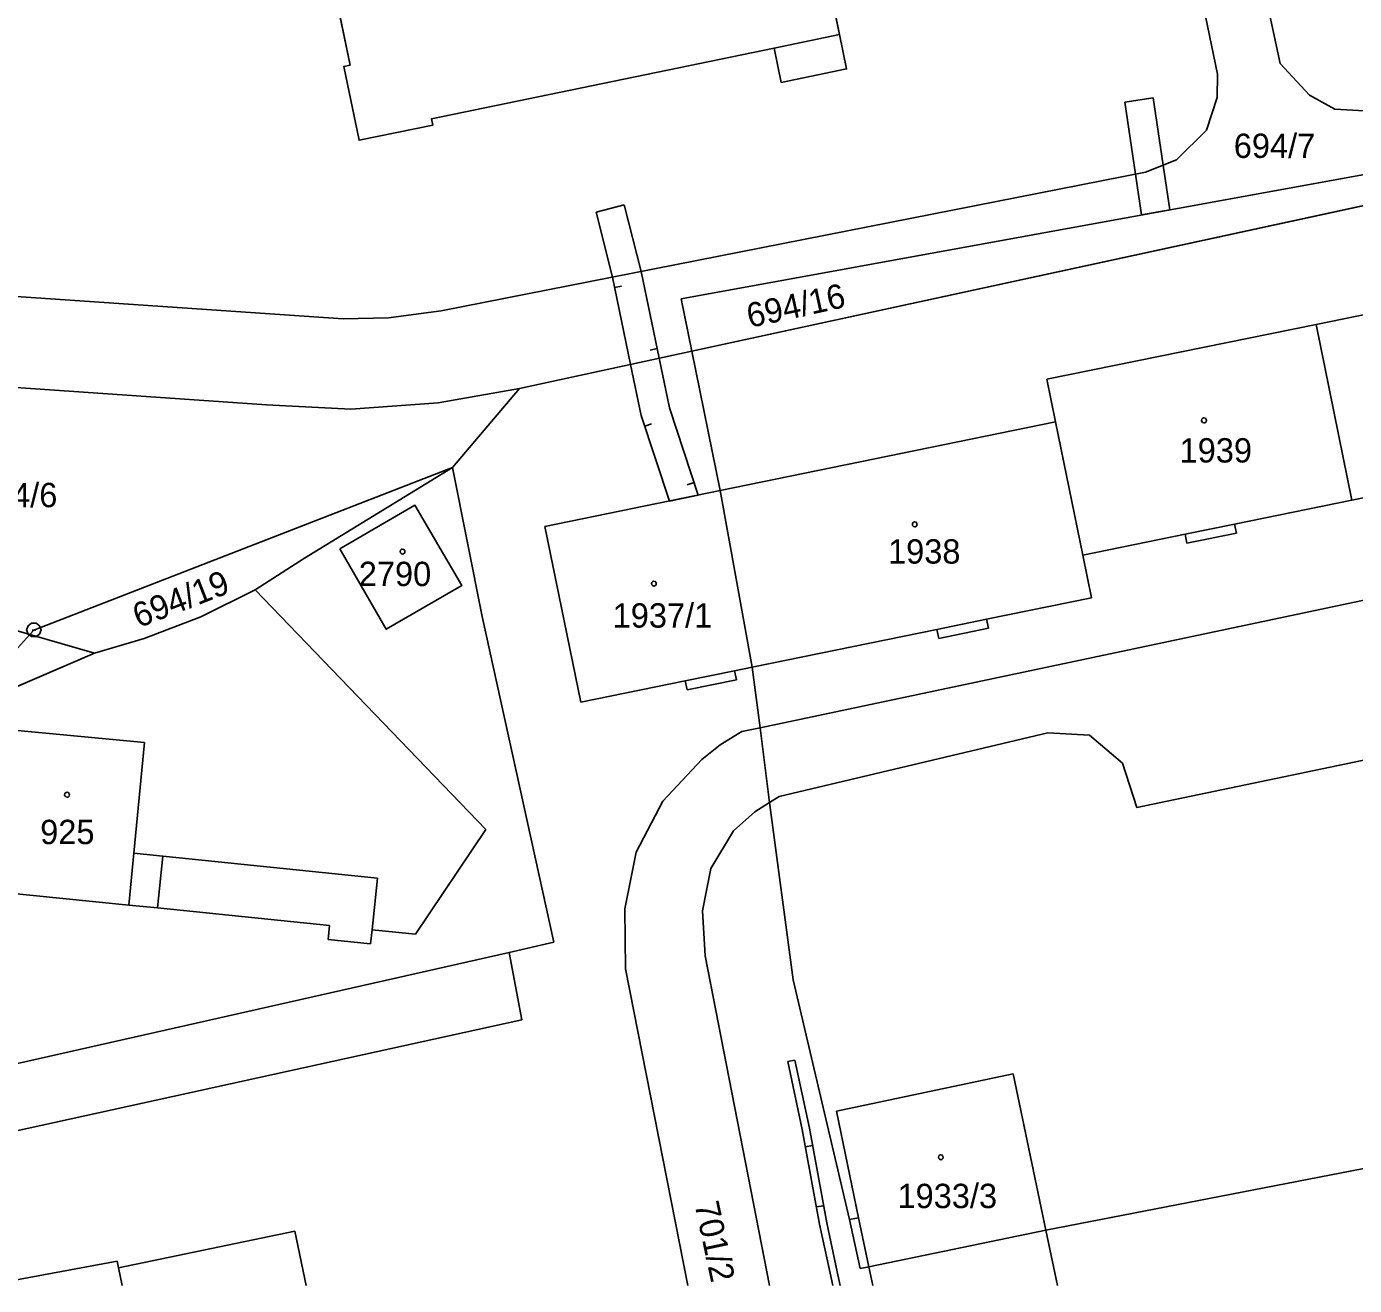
# Model space of a CAD drawing. Extents: x -777309 to -774195, y -1144706 to -1143600.
# Drawn here: x -775094.2 to -775001.5, y -1144700 to -1144612.1 of the extents above; entities that cross this region are included whole.
import ezdxf

# ---------------------------------------------------------------- set-up
doc = ezdxf.new("R2010")
doc.units = 0
for name, color, linetype in [('1', 7, 'Continuous'), ('11', 7, 'Continuous'), ('12', 7, 'Continuous'), ('13', 7, 'Continuous'), ('2', 7, 'Continuous'), ('4', 7, 'Continuous'), ('5', 7, 'Continuous'), ('8', 7, 'Continuous')]:
    doc.layers.add(name, color=color, linetype=linetype)

msp = doc.modelspace()

# ---------------------------------------------------------------- linework, layer by layer
at = {"layer": '1'}
for p, q in [((-775075.83, -1144594.37), (-775071.62, -1144614.78)), ((-775037.44, -1144612.65), (-775040.4, -1144598.45)), ((-775006.67, -1144614.66), (-775009.6, -1144600.96)), ((-775013.87, -1144601.8), (-775011.04, -1144615.41)), ((-775036.95, -1144615.04), (-775037.44, -1144612.65)), ((-775065.93, -1144618.52), (-775042.01, -1144613.59)), ((-774952.86, -1144614.17), (-775047.76, -1144634.76)), ((-775042.01, -1144613.59), (-775041.52, -1144615.98)), ((-775071.62, -1144614.78), (-775072.06, -1144614.87)), ((-775072.06, -1144614.87), (-775070.99, -1144620.02)), ((-775041.52, -1144615.98), (-775036.95, -1144615.04)), ((-775004.63, -1144616.87), (-775006.67, -1144614.66)), ((-775011.04, -1144615.41), (-775011.07, -1144617.04)), ((-775011.07, -1144617.04), (-775011.81, -1144619.33)), ((-775002.85, -1144617.85), (-775004.63, -1144616.87)), ((-774999.95, -1144618.02), (-775002.85, -1144617.85)), ((-775070.99, -1144620.02), (-775065.84, -1144618.96)), ((-775065.84, -1144618.96), (-775065.93, -1144618.52)), ((-775011.81, -1144619.33), (-775013.91, -1144621.39)), ((-775048.51, -1144631.09), (-774995.24, -1144621.4)), ((-775013.91, -1144621.39), (-775016.08, -1144622.26)), ((-775016.08, -1144622.26), (-775065.26, -1144631.94)), ((-775004.17, -1144632.88), (-774985.36, -1144629.03)), ((-775072.11, -1144632.49), (-775108.25, -1144630.03)), ((-775065.26, -1144631.94), (-775068.93, -1144632.43)), ((-775048.51, -1144631.09), (-775047.76, -1144634.76)), ((-775068.93, -1144632.43), (-775072.11, -1144632.49)), ((-775022.97, -1144636.72), (-775004.17, -1144632.88)), ((-775001.66, -1144645.15), (-775004.17, -1144632.88)), ((-775047.76, -1144634.76), (-775059.8, -1144637.37)), ((-775047.76, -1144634.76), (-775045.78, -1144644.49)), ((-775106.37, -1144636.49), (-775077.45, -1144638.5)), ((-774926.57, -1144636.48), (-775042.99, -1144661.05)), ((-775065.48, -1144638.36), (-775059.8, -1144637.37)), ((-775059.8, -1144637.37), (-775064.48, -1144642.88)), ((-775022.36, -1144639.7), (-775022.97, -1144636.72)), ((-775077.45, -1144638.5), (-775071.57, -1144638.81)), ((-775071.57, -1144638.81), (-775065.48, -1144638.36)), ((-775045.78, -1144644.49), (-775022.36, -1144639.7)), ((-775020.46, -1144649), (-775022.36, -1144639.7)), ((-775093.7, -1144654.23), (-775064.48, -1144642.88)), ((-775064.48, -1144642.88), (-775074.81, -1144649.2)), ((-775064.48, -1144642.88), (-775062.41, -1144653.28)), ((-774992.16, -1144643.21), (-775001.66, -1144645.15)), ((-775058.02, -1144647), (-775045.78, -1144644.49)), ((-775045.78, -1144644.49), (-775043.55, -1144656.82)), ((-775001.66, -1144645.15), (-775009.86, -1144646.83)), ((-775009.86, -1144646.83), (-775009.73, -1144647.46)), ((-775055.51, -1144659.27), (-775058.02, -1144647)), ((-775013.32, -1144647.54), (-775020.46, -1144649)), ((-775013.19, -1144648.16), (-775013.32, -1144647.54)), ((-775009.73, -1144647.46), (-775013.19, -1144648.16)), ((-775074.81, -1144649.2), (-775078.24, -1144651.43)), ((-775020.46, -1144649), (-775019.85, -1144651.97)), ((-775078.24, -1144651.43), (-775082.04, -1144653.3)), ((-775062.14, -1144668.17), (-775078.24, -1144651.43)), ((-775101.75, -1144652.28), (-775093.98, -1144654.54)), ((-775019.85, -1144651.97), (-775027.18, -1144653.47)), ((-775082.04, -1144653.3), (-775086, -1144654.83)), ((-775062.41, -1144653.28), (-775057.4, -1144676.03)), ((-775093.98, -1144654.54), (-775093.7, -1144654.23)), ((-775043.55, -1144656.82), (-775030.64, -1144654.18)), ((-775030.51, -1144654.81), (-775030.64, -1144654.18)), ((-775027.05, -1144654.1), (-775030.51, -1144654.81)), ((-775027.18, -1144653.47), (-775027.05, -1144654.1)), ((-775098.79, -1144659.85), (-775093.98, -1144654.54)), ((-775093.98, -1144654.54), (-775089.48, -1144655.85)), ((-775086, -1144654.83), (-775089.48, -1144655.85)), ((-775016.68, -1144666.62), (-774960.12, -1144654.79)), ((-775098.79, -1144659.85), (-775089.48, -1144655.85)), ((-775043.55, -1144656.82), (-775044.77, -1144657.07)), ((-775043.55, -1144656.82), (-775042.99, -1144661.05)), ((-775048.22, -1144657.78), (-775055.51, -1144659.27)), ((-775048.09, -1144658.41), (-775048.22, -1144657.78)), ((-775044.64, -1144657.7), (-775048.09, -1144658.41)), ((-775044.77, -1144657.07), (-775044.64, -1144657.7)), ((-775044.27, -1144661.32), (-775045.79, -1144662.25)), ((-775042.99, -1144661.05), (-775044.27, -1144661.32)), ((-775042.99, -1144661.05), (-775042.33, -1144666.27)), ((-775041.66, -1144665.85), (-775022.9, -1144661.4)), ((-775022.9, -1144661.4), (-775019.98, -1144661.57)), ((-775019.98, -1144661.57), (-775017.69, -1144663.53)), ((-775045.79, -1144662.25), (-775047.06, -1144663.26)), ((-775047.06, -1144663.26), (-775049.78, -1144666.17)), ((-775017.69, -1144663.53), (-775016.68, -1144666.62)), ((-775049.78, -1144666.17), (-775051.65, -1144669.73)), ((-775043.37, -1144666.93), (-775042.33, -1144666.27)), ((-775042.33, -1144666.27), (-775041.66, -1144665.85)), ((-775040.69, -1144678.65), (-775042.33, -1144666.27)), ((-775044.85, -1144668.25), (-775043.37, -1144666.93)), ((-775067.06, -1144675.47), (-775062.14, -1144668.17)), ((-775046.44, -1144670.89), (-775044.85, -1144668.25)), ((-775051.65, -1144669.73), (-775052.43, -1144673.69)), ((-775047.01, -1144673.83), (-775046.44, -1144670.89)), ((-775097.27, -1144672.41), (-775087.08, -1144673.44)), ((-775087.08, -1144673.44), (-775085.07, -1144673.62)), ((-775085.07, -1144673.62), (-775073.05, -1144674.86)), ((-775052.43, -1144673.69), (-775052.39, -1144677.89)), ((-775046.83, -1144676.98), (-775047.01, -1144673.83)), ((-775073.05, -1144674.86), (-775073.16, -1144675.85)), ((-775070.19, -1144676.15), (-775070.09, -1144675.16)), ((-775070.09, -1144675.16), (-775067.06, -1144675.47)), ((-775073.16, -1144675.85), (-775070.19, -1144676.15)), ((-775057.4, -1144676.03), (-775060.52, -1144676.74)), ((-775060.52, -1144676.74), (-775109.1, -1144687.73)), ((-775042.342, -1144700), (-775046.83, -1144676.98)), ((-775052.39, -1144677.89), (-775048.03, -1144700)), ((-775040.69, -1144678.65), (-775036.74, -1144695.4)), ((-775025.32, -1144685.23), (-775037.66, -1144687.82)), ((-775025.32, -1144685.23), (-775023.03, -1144696.15)), ((-775036.11, -1144695.27), (-775037.66, -1144687.82)), ((-775023.03, -1144696.15), (-774984.81, -1144688.7)), ((-775036.74, -1144695.4), (-775036.11, -1144695.27)), ((-775036.01, -1144698.81), (-775036.74, -1144695.4)), ((-775075.47, -1144696.21), (-775087.79, -1144698.78)), ((-775074.68, -1144700), (-775075.47, -1144696.21)), ((-775023.03, -1144696.15), (-775035.4, -1144698.69)), ((-775023.03, -1144696.15), (-775022.223, -1144700)), ((-775035.4, -1144698.69), (-775036.01, -1144698.81)), ((-775035.13, -1144700), (-775035.4, -1144698.69)), ((-775087.79, -1144698.78), (-775087.534, -1144700))]:
    msp.add_line(p, q, dxfattribs=at)
msp.add_lwpolyline([(-775072.34, -1144648.55), (-775067.09, -1144645.52), (-775063.82, -1144651.12), (-775069.1, -1144654.17)], close=True, dxfattribs=at)
at = {"layer": '11'}
for points in [[(-775040.4, -1144598.45), (-775037.44, -1144612.65), (-775036.95, -1144615.04), (-775041.52, -1144615.98), (-775042.01, -1144613.59), (-775065.93, -1144618.52), (-775065.84, -1144618.96), (-775070.99, -1144620.02), (-775072.06, -1144614.87), (-775071.62, -1144614.78), (-775075.83, -1144594.37)], [(-774901, -1144684.4), (-774908.35, -1144649.03), (-774909.67, -1144645.42), (-774911.03, -1144642.74), (-774912.97, -1144640.51), (-774916.07, -1144638.06), (-774918.73, -1144636.66), (-774920.42, -1144636.32), (-774921.69, -1144636.06), (-774922.39, -1144636.1), (-774923.79, -1144636.05), (-774928.78, -1144612.51), (-774929.9, -1144607.21), (-774953.35, -1144612.05), (-774952.86, -1144614.17), (-775047.76, -1144634.76), (-775059.8, -1144637.37), (-775064.48, -1144642.88), (-775074.81, -1144649.2), (-775078.24, -1144651.43), (-775082.04, -1144653.3), (-775086, -1144654.83), (-775089.48, -1144655.85), (-775098.79, -1144659.85)]]:
    msp.add_lwpolyline(points, dxfattribs=at)
at = {"layer": '12'}
for p, q in [((-775075.83, -1144594.37), (-775071.62, -1144614.78)), ((-775037.44, -1144612.65), (-775040.4, -1144598.45)), ((-775042.01, -1144613.59), (-775037.44, -1144612.65)), ((-775065.93, -1144618.52), (-775042.01, -1144613.59)), ((-775071.62, -1144614.78), (-775072.06, -1144614.87)), ((-775072.06, -1144614.87), (-775070.99, -1144620.02)), ((-775070.99, -1144620.02), (-775065.84, -1144618.96)), ((-775065.84, -1144618.96), (-775065.93, -1144618.52)), ((-775004.17, -1144632.88), (-774985.36, -1144629.03)), ((-775022.97, -1144636.72), (-775004.17, -1144632.88)), ((-775022.36, -1144639.7), (-775022.97, -1144636.72)), ((-775045.78, -1144644.49), (-775022.36, -1144639.7)), ((-775020.46, -1144649), (-775022.36, -1144639.7)), ((-775020.46, -1144649), (-775022.36, -1144639.7)), ((-774992.16, -1144643.21), (-775001.66, -1144645.15)), ((-775058.02, -1144647), (-775045.78, -1144644.49)), ((-775001.66, -1144645.15), (-775009.86, -1144646.83)), ((-775013.32, -1144647.54), (-775009.86, -1144646.83)), ((-775055.51, -1144659.27), (-775058.02, -1144647)), ((-775013.32, -1144647.54), (-775020.46, -1144649)), ((-775020.46, -1144649), (-775019.85, -1144651.97)), ((-775019.85, -1144651.97), (-775027.18, -1144653.47)), ((-775043.55, -1144656.82), (-775030.64, -1144654.18)), ((-775030.64, -1144654.18), (-775027.18, -1144653.47)), ((-775043.55, -1144656.82), (-775044.77, -1144657.07)), ((-775048.22, -1144657.78), (-775055.51, -1144659.27)), ((-775048.22, -1144657.78), (-775044.77, -1144657.07)), ((-775085.99, -1144662.09), (-775096.1, -1144661.12)), ((-775086.73, -1144669.8), (-775085.99, -1144662.09)), ((-775086.73, -1144669.8), (-775087.08, -1144673.44)), ((-775097.27, -1144672.41), (-775087.08, -1144673.44)), ((-775025.32, -1144685.23), (-775037.66, -1144687.82)), ((-775025.32, -1144685.23), (-775023.03, -1144696.15)), ((-775036.11, -1144695.27), (-775037.66, -1144687.82)), ((-775036.11, -1144695.27), (-775035.4, -1144698.69)), ((-775075.47, -1144696.21), (-775087.79, -1144698.78)), ((-775074.68, -1144700), (-775075.47, -1144696.21)), ((-775023.03, -1144696.15), (-775022.223, -1144700)), ((-775035.13, -1144700), (-775035.4, -1144698.69)), ((-775087.79, -1144698.78), (-775087.534, -1144700))]:
    msp.add_line(p, q, dxfattribs=at)
msp.add_lwpolyline([(-775072.34, -1144648.55), (-775067.09, -1144645.52), (-775063.82, -1144651.12), (-775069.1, -1144654.17)], close=True, dxfattribs=at)
at = {"layer": '13'}
for p, q in [((-775017.52, -1144617.36), (-775015.55, -1144617.06)), ((-775015.55, -1144617.06), (-775014.84, -1144621.76)), ((-775016.77, -1144622.4), (-775017.52, -1144617.36)), ((-775014.84, -1144621.76), (-775014.38, -1144624.88)), ((-775016.35, -1144625.24), (-775016.77, -1144622.4)), ((-775054.45, -1144625.04), (-775052.48, -1144624.54)), ((-775052.48, -1144624.54), (-775051.3, -1144629.19)), ((-775053.3, -1144629.58), (-775054.45, -1144625.04)), ((-775014.38, -1144624.88), (-775016.35, -1144625.24)), ((-775051.3, -1144629.19), (-775050.04, -1144635.25)), ((-775052.03, -1144635.69), (-775053.3, -1144629.58)), ((-775053.149, -1144630.305), (-775052.66, -1144630.203)), ((-775050.18, -1144634.575), (-775050.67, -1144634.676)), ((-775051.29, -1144639.24), (-775052.03, -1144635.69)), ((-775050.04, -1144635.25), (-775049.32, -1144638.7)), ((-775049.32, -1144645.22), (-775051.29, -1144639.24)), ((-775049.32, -1144638.7), (-775047.31, -1144644.8)), ((-775051.041, -1144639.996), (-775050.566, -1144639.84)), ((-775047.599, -1144643.924), (-775048.074, -1144644.08)), ((-775047.31, -1144644.8), (-775049.32, -1144645.22)), ((-775041.06, -1144684.37), (-775040.57, -1144684.26)), ((-775040.05, -1144689.12), (-775041.06, -1144684.37)), ((-775040.57, -1144684.26), (-775039.55, -1144689.02)), ((-775038.84, -1144695.73), (-775040.05, -1144689.12)), ((-775039.55, -1144689.02), (-775038.34, -1144695.63)), ((-775039.83, -1144690.32), (-775039.339, -1144690.23)), ((-775038.56, -1144694.43), (-775039.052, -1144694.52)), ((-775038.1, -1144699.14), (-775038.84, -1144695.73)), ((-775038.34, -1144695.63), (-775037.62, -1144699.04)), ((-775097.025, -1144700), (-775087.89, -1144698.31)), ((-775087.89, -1144698.31), (-775087.79, -1144698.78)), ((-775087.79, -1144698.78), (-775087.537, -1144700)), ((-775037.908, -1144700), (-775038.1, -1144699.14)), ((-775037.62, -1144699.04), (-775037.405, -1144700))]:
    msp.add_line(p, q, dxfattribs=at)
at = {"layer": '4'}
for p, q in [((-775042.01, -1144613.59), (-775037.44, -1144612.65)), ((-775013.32, -1144647.54), (-775009.86, -1144646.83)), ((-775030.64, -1144654.18), (-775027.18, -1144653.47)), ((-775048.22, -1144657.78), (-775044.77, -1144657.07)), ((-775085.99, -1144662.09), (-775096.1, -1144661.12)), ((-775086.73, -1144669.8), (-775085.99, -1144662.09)), ((-775086.73, -1144669.8), (-775087.08, -1144673.44)), ((-775084.7, -1144670.01), (-775086.73, -1144669.8)), ((-775085.07, -1144673.62), (-775084.7, -1144670.01)), ((-775069.71, -1144671.55), (-775084.7, -1144670.01)), ((-775070.09, -1144675.16), (-775069.71, -1144671.55)), ((-775059.63, -1144681.44), (-775060.52, -1144676.74)), ((-775108.83, -1144692.26), (-775059.63, -1144681.44)), ((-775036.11, -1144695.27), (-775035.4, -1144698.69))]:
    msp.add_line(p, q, dxfattribs=at)
at = {"layer": '5'}
for points in [[(-775012, -1144639.42), (-775011.9, -1144639.44), (-775011.85, -1144639.53), (-775011.83, -1144639.59), (-775011.85, -1144639.68), (-775011.93, -1144639.75), (-775012, -1144639.76), (-775012.09, -1144639.73), (-775012.15, -1144639.67), (-775012.17, -1144639.59), (-775012.15, -1144639.5), (-775012.07, -1144639.43)], [(-775032.19, -1144646.68), (-775032.09, -1144646.7), (-775032.04, -1144646.79), (-775032.02, -1144646.85), (-775032.04, -1144646.94), (-775032.12, -1144647.01), (-775032.19, -1144647.02), (-775032.28, -1144646.99), (-775032.34, -1144646.93), (-775032.36, -1144646.85), (-775032.34, -1144646.76), (-775032.26, -1144646.69)], [(-775067.96, -1144648.58), (-775067.86, -1144648.6), (-775067.81, -1144648.69), (-775067.79, -1144648.75), (-775067.81, -1144648.84), (-775067.89, -1144648.91), (-775067.96, -1144648.92), (-775068.05, -1144648.89), (-775068.11, -1144648.83), (-775068.13, -1144648.75), (-775068.11, -1144648.66), (-775068.03, -1144648.59)], [(-775050.41, -1144650.82), (-775050.31, -1144650.84), (-775050.26, -1144650.93), (-775050.24, -1144650.99), (-775050.26, -1144651.08), (-775050.34, -1144651.15), (-775050.41, -1144651.16), (-775050.5, -1144651.13), (-775050.56, -1144651.07), (-775050.58, -1144650.99), (-775050.56, -1144650.9), (-775050.48, -1144650.83)], [(-775091.39, -1144665.56), (-775091.29, -1144665.58), (-775091.24, -1144665.67), (-775091.22, -1144665.73), (-775091.24, -1144665.82), (-775091.32, -1144665.89), (-775091.39, -1144665.9), (-775091.48, -1144665.87), (-775091.54, -1144665.81), (-775091.56, -1144665.73), (-775091.54, -1144665.64), (-775091.46, -1144665.57)], [(-775030.37, -1144690.88), (-775030.27, -1144690.9), (-775030.22, -1144690.99), (-775030.2, -1144691.05), (-775030.22, -1144691.14), (-775030.3, -1144691.21), (-775030.37, -1144691.22), (-775030.46, -1144691.19), (-775030.52, -1144691.13), (-775030.54, -1144691.05), (-775030.52, -1144690.96), (-775030.44, -1144690.89)]]:
    msp.add_lwpolyline(points, close=True, dxfattribs=at)
at = {"layer": '8'}
msp.add_line((-775093.82, -1144654.23), (-775093.58, -1144654.23), dxfattribs=at)
msp.add_lwpolyline([(-775093.55, -1144653.75), (-775093.3, -1144653.93), (-775093.2, -1144654.22), (-775093.3, -1144654.51), (-775093.55, -1144654.69), (-775093.86, -1144654.69), (-775094.11, -1144654.51), (-775094.21, -1144654.22), (-775094.11, -1144653.93), (-775093.86, -1144653.75)], close=True, dxfattribs=at)

# ---------------------------------------------------------------- texts
at = {"layer": '2'}
for s, p in [('694/7', (-775009.913, -1144621.26)), ('1939', (-775013.697, -1144642.53)), ('694/6', (-775097.753, -1144645.65)), ('1938', (-775034.057, -1144649.59)), ('2790', (-775071.014, -1144651.16)), ('1937/1', (-775053.287, -1144654.06)), ('925', (-775093.263, -1144669.18)), ('1933/3', (-775033.397, -1144694.6))]:
    msp.add_text(s, height=1.7, dxfattribs=at).set_placement(p)
for s, rotation, p in [('694/16', 12.2613, (-775043.721, -1144633.134)), ('694/19', 21.19944, (-775086.387, -1144654.101)), ('701/2', 282.06712, (-775047.58, -1144694.312))]:
    msp.add_text(s, height=1.7, rotation=rotation, dxfattribs=at).set_placement(p)

doc.saveas('drawing.dxf')
